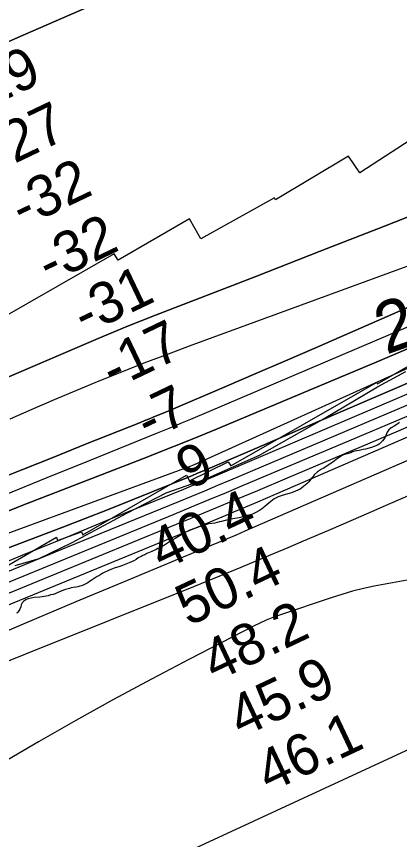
# Model space of a CAD drawing. Extents: x 3177385 to 3215275, y 903885 to 929304.
# Drawn here: x 3197368 to 3197989, y 912486 to 913822 of the extents above; entities that cross this region are included whole.
import ezdxf

# ---------------------------------------------------------------- set-up
doc = ezdxf.new("R2010")
doc.units = 0
for name, color, linetype in [('V-RIVR-EDGE', 7, 'Continuous'), ('V-RIVR-IDEN', 7, 'Continuous'), ('V-RIVR-RANG', 7, 'Continuous'), ('V-RRAP-RVMT', 7, 'Continuous'), ('V-SITE-VEGE', 7, 'Continuous'), ('V-TOPO-BNDY', 7, 'Continuous'), ('V-TOPO-DPTH', 7, 'Continuous'), ('V-TOPO-MAJR', 7, 'Continuous'), ('V-TOPO-MINR', 7, 'Continuous'), ('V-TOPO-WATR', 7, 'Continuous')]:
    doc.layers.add(name, color=color, linetype=linetype)

msp = doc.modelspace()

# ---------------------------------------------------------------- linework, layer by layer
at = {"layer": 'V-RIVR-EDGE'}
msp.add_lwpolyline([(3197365.4, 912930.6), (3197404.5, 912941.8), (3197458, 912967.8), (3197546.8, 913015.4), (3197610.4, 913048.7), (3197673.9, 913070.7), (3197762.2, 913109.6), (3197867.1, 913168.9), (3197953.3, 913220.4), (3197999.5, 913245.5)], dxfattribs=at)
at = {"layer": 'V-RRAP-RVMT'}
for points in [[(3198676.7, 913864.1), (3198655.3, 913896.8), (3198542.3, 913824.7), (3198538.1, 913830.1), (3198431.4, 913761.2), (3198410.7, 913790.5), (3198293, 913713.7), (3198279.5, 913731.9), (3198168.4, 913660.4), (3198123.3, 913659.6), (3198109.2, 913680.1), (3198031.3, 913630.7), (3198028.1, 913634.7), (3197925, 913567.7), (3197906.3, 913594.7), (3197788, 913524), (3197786.3, 913527.5), (3197666.9, 913460.6), (3197648.1, 913493.3), (3197532.6, 913426.2), (3197526.1, 913436.6), (3197292.5, 913302.6)], [(3197337.8, 912921.7), (3197432.4, 912976.4), (3197434.2, 912970.9), (3197473, 912985.2), (3197475.3, 912980.1), (3197643.3, 913077), (3197648.2, 913068.1), (3197711.1, 913098.9), (3197715.3, 913092.4), (3197951.6, 913227.8), (3197953.3, 913225.1), (3198007.2, 913256.1)]]:
    msp.add_lwpolyline(points, dxfattribs=at)
at = {"layer": 'V-SITE-VEGE'}
for p, q in [((3197980.4, 913156.6), (3197975.7, 913153.7)), ((3197986.7, 913160.2), (3197980.4, 913156.6)), ((3197989.2, 913162.4), (3197986.7, 913160.2)), ((3197969.1, 913147.1), (3197965.9, 913138.6)), ((3197972.1, 913150.5), (3197969.1, 913147.1)), ((3197975.7, 913153.7), (3197972.1, 913150.5)), ((3197956.1, 913127.2), (3197953.4, 913125.8)), ((3197958.5, 913129.4), (3197956.1, 913127.2)), ((3197961.5, 913132.8), (3197958.5, 913129.4)), ((3197963.7, 913135.5), (3197961.5, 913132.8)), ((3197965.9, 913138.6), (3197963.7, 913135.5)), ((3197912.9, 913114.8), (3197909.9, 913113.6)), ((3197919.2, 913116.7), (3197912.9, 913114.8)), ((3197923.6, 913117.2), (3197919.2, 913116.7)), ((3197930.2, 913118.6), (3197923.6, 913117.2)), ((3197933.9, 913119.1), (3197930.2, 913118.6)), ((3197943.6, 913121.9), (3197933.9, 913119.1)), ((3197953.4, 913125.8), (3197943.6, 913121.9)), ((3197886.5, 913102.3), (3197881.1, 913098.2)), ((3197895, 913108.3), (3197886.5, 913102.3)), ((3197898.5, 913110), (3197895, 913108.3)), ((3197901.9, 913111), (3197898.5, 913110)), ((3197909.9, 913113.6), (3197901.9, 913111)), ((3197865.2, 913088), (3197862.3, 913086.8)), ((3197868.1, 913089.5), (3197865.2, 913088)), ((3197871.8, 913092.4), (3197868.1, 913089.5)), ((3197881.1, 913098.2), (3197871.8, 913092.4)), ((3197848.8, 913075.2), (3197846.6, 913072)), ((3197850.5, 913077.9), (3197848.8, 913075.2)), ((3197855.9, 913082.7), (3197850.5, 913077.9)), ((3197862.3, 913086.8), (3197855.9, 913082.7)), ((3197839, 913063.3), (3197833.6, 913058.7)), ((3197841.9, 913066.5), (3197839, 913063.3)), ((3197846.6, 913072), (3197841.9, 913066.5)), ((3197810.3, 913047.2), (3197800.6, 913044.8)), ((3197814, 913048.3), (3197810.3, 913047.2)), ((3197820.4, 913051), (3197814, 913048.3)), ((3197827.9, 913054.6), (3197820.4, 913051)), ((3197830.4, 913056.5), (3197827.9, 913054.6)), ((3197833.6, 913058.7), (3197830.4, 913056.5)), ((3197780.3, 913034.2), (3197777.1, 913031.7)), ((3197785.9, 913038.8), (3197780.3, 913034.2)), ((3197792.5, 913042.1), (3197785.9, 913038.8)), ((3197800.6, 913044.8), (3197792.5, 913042.1)), ((3197765.4, 913022.1), (3197761.9, 913019.6)), ((3197767.8, 913024.2), (3197765.4, 913022.1)), ((3197770.5, 913026.2), (3197767.8, 913024.2)), ((3197777.1, 913031.7), (3197770.5, 913026.2)), ((3197729.2, 913007.9), (3197718.5, 913006.5)), ((3197737.7, 913010.3), (3197729.2, 913007.9)), ((3197741.2, 913011.5), (3197737.7, 913010.3)), ((3197744.6, 913012.4), (3197741.2, 913011.5)), ((3197748.7, 913013.4), (3197744.6, 913012.4)), ((3197751.7, 913014.6), (3197748.7, 913013.4)), ((3197755.1, 913015.8), (3197751.7, 913014.6)), ((3197761.9, 913019.6), (3197755.1, 913015.8)), ((3197665.7, 912993.6), (3197662.6, 912992.7)), ((3197672.3, 912996), (3197665.7, 912993.6)), ((3197675.7, 912996.8), (3197672.3, 912996)), ((3197679.2, 912997.9), (3197675.7, 912996.8)), ((3197684.5, 912998.6), (3197679.2, 912997.9)), ((3197689.2, 912999.1), (3197684.5, 912998.6)), ((3197697, 913001.3), (3197689.2, 912999.1)), ((3197700.4, 913002), (3197697, 913001.3)), ((3197714.1, 913005.5), (3197700.4, 913002)), ((3197718.5, 913006.5), (3197714.1, 913005.5)), ((3197636.7, 912981.9), (3197633.2, 912979.4)), ((3197648.9, 912987.9), (3197636.7, 912981.9)), ((3197655, 912990.3), (3197648.9, 912987.9)), ((3197658.4, 912991.2), (3197655, 912990.3)), ((3197662.6, 912992.7), (3197658.4, 912991.2)), ((3197614.4, 912967.9), (3197607.8, 912963.3)), ((3197617.6, 912969.8), (3197614.4, 912967.9)), ((3197620, 912971.7), (3197617.6, 912969.8)), ((3197624.9, 912974.6), (3197620, 912971.7)), ((3197627.9, 912976.1), (3197624.9, 912974.6)), ((3197633.2, 912979.4), (3197627.9, 912976.1)), ((3197587, 912953.4), (3197579, 912949.8)), ((3197594.3, 912956.3), (3197587, 912953.4)), ((3197597, 912958), (3197594.3, 912956.3)), ((3197600.2, 912959.2), (3197597, 912958)), ((3197603.6, 912961.1), (3197600.2, 912959.2)), ((3197607.8, 912963.3), (3197603.6, 912961.1)), ((3197561.6, 912940.4), (3197557.9, 912938.2)), ((3197565.3, 912942.8), (3197561.6, 912940.4)), ((3197569.7, 912945), (3197565.3, 912942.8)), ((3197572.8, 912946.9), (3197569.7, 912945)), ((3197575.8, 912948.1), (3197572.8, 912946.9)), ((3197579, 912949.8), (3197575.8, 912948.1)), ((3197535.2, 912929.1), (3197525.9, 912926.2)), ((3197539.6, 912930.3), (3197535.2, 912929.1)), ((3197550.3, 912935.1), (3197539.6, 912930.3)), ((3197557.9, 912938.2), (3197550.3, 912935.1)), ((3197501.2, 912913.9), (3197498.3, 912912.5)), ((3197504.7, 912915.8), (3197501.2, 912913.9)), ((3197507.6, 912918), (3197504.7, 912915.8)), ((3197516.9, 912922.6), (3197507.6, 912918)), ((3197520.8, 912924), (3197516.9, 912922.6)), ((3197525.9, 912926.2), (3197520.8, 912924)), ((3197480.2, 912900.6), (3197477, 912899.4)), ((3197483.1, 912902.3), (3197480.2, 912900.6)), ((3197486.1, 912904.3), (3197483.1, 912902.3)), ((3197489, 912906.4), (3197486.1, 912904.3)), ((3197492.2, 912908.4), (3197489, 912906.4)), ((3197498.3, 912912.5), (3197492.2, 912908.4)), ((3197437.2, 912887.7), (3197433.6, 912886.3)), ((3197444.1, 912890.6), (3197437.2, 912887.7)), ((3197447.2, 912891.6), (3197444.1, 912890.6)), ((3197453.6, 912893.2), (3197447.2, 912891.6)), ((3197456.5, 912894.2), (3197453.6, 912893.2)), ((3197459.7, 912894.9), (3197456.5, 912894.2)), ((3197463.8, 912895.6), (3197459.7, 912894.9)), ((3197467, 912895.8), (3197463.8, 912895.6)), ((3197470.2, 912896.8), (3197467, 912895.8)), ((3197473.1, 912897.3), (3197470.2, 912896.8)), ((3197477, 912899.4), (3197473.1, 912897.3)), ((3197383.5, 912875.1), (3197379.6, 912872.9)), ((3197386.7, 912876.3), (3197383.5, 912875.1)), ((3197396.2, 912878.7), (3197386.7, 912876.3)), ((3197405.5, 912879.1), (3197396.2, 912878.7)), ((3197409.1, 912879.8), (3197405.5, 912879.1)), ((3197412.3, 912880.1), (3197409.1, 912879.8)), ((3197418.9, 912881.5), (3197412.3, 912880.1)), ((3197422.8, 912882.7), (3197418.9, 912881.5)), ((3197427.2, 912883.6), (3197422.8, 912882.7)), ((3197430.6, 912884.8), (3197427.2, 912883.6)), ((3197433.6, 912886.3), (3197430.6, 912884.8)), ((3197374.4, 912863.5), (3197372.9, 912859.8)), ((3197375.4, 912866.9), (3197374.4, 912863.5)), ((3197376.7, 912869.8), (3197375.4, 912866.9)), ((3197379.6, 912872.9), (3197376.7, 912869.8)), ((3197368.5, 912853.8), (3197367.5, 912853)), ((3197371.2, 912856.9), (3197368.5, 912853.8)), ((3197372.9, 912859.8), (3197371.2, 912856.9))]:
    msp.add_line(p, q, dxfattribs=at)
at = {"layer": 'V-TOPO-BNDY'}
msp.add_lwpolyline([(3212104.8, 927455), (3211654.7, 925302.3), (3210557.1, 922651.3), (3209209.3, 920082.8), (3207894, 918536.9), (3206269, 917198.2), (3204190, 915875.2), (3202489, 914709.7), (3200914, 913922.2), (3198614.5, 912914.1), (3196094.5, 911748.6), (3194267.5, 911118.6), (3192913, 910488.6), (3191155.6, 909558.2), (3212939.7, 909531.5)], dxfattribs=at)
at = {"layer": 'V-TOPO-DPTH'}
for points in [[(3199243.5, 914059.7), (3199154.5, 914014.8), (3199065.5, 913970.1), (3198976.3, 913925.6), (3198887.1, 913881.3), (3198607.4, 913742.9), (3198578.8, 913729.2), (3198549.9, 913715.9), (3198520.8, 913703.3), (3198491.5, 913691.2), (3198173.5, 913564), (3198069.2, 913522.6), (3197964.9, 913481.3), (3197860.4, 913440.5), (3197755.9, 913399.8), (3197593.4, 913337), (3197570.1, 913327.8), (3197546.7, 913318.5), (3197523.5, 913308.9), (3197500.4, 913299.1), (3197177.6, 913160.9)], [(3197177.6, 913160.9), (3197500.4, 913299.1), (3197523.5, 913308.9), (3197546.7, 913318.5), (3197570.1, 913327.8), (3197593.4, 913337), (3197755.9, 913399.8), (3197860.4, 913440.5), (3197964.9, 913481.3), (3198069.2, 913522.6), (3198173.5, 913564), (3198491.5, 913691.2), (3198520.8, 913703.3), (3198549.9, 913715.9), (3198578.8, 913729.2), (3198607.4, 913742.9), (3198887.1, 913881.3), (3198976.3, 913925.6), (3199065.5, 913970.1), (3199154.5, 914014.8), (3199243.5, 914059.7)], [(3199473, 914010.7), (3198670.3, 913642.9), (3198634.5, 913626.6), (3198598.6, 913610.4), (3198562.7, 913594.4), (3198526.6, 913578.5), (3197899.9, 913304.1), (3197852, 913283.2), (3197804.2, 913262.5), (3197756.2, 913241.9), (3197708.3, 913221.4), (3197614.9, 913181.7), (3197613.6, 913181.1), (3197609.5, 913179.4), (3197597.7, 913174.6), (3197590.5, 913171.6), (3197583.2, 913168.7), (3197576, 913165.7), (3197568.7, 913162.8), (3197479.8, 913127.2), (3197428, 913106.5), (3197376.3, 913085.8), (3197324.6, 913065.1)], [(3199473, 914010.7), (3198670.3, 913642.9), (3198634.5, 913626.6), (3198598.6, 913610.4), (3198562.7, 913594.4), (3198526.6, 913578.5), (3197899.9, 913304.1), (3197852, 913283.2), (3197804.2, 913262.5), (3197756.2, 913241.9), (3197708.3, 913221.4), (3197614.9, 913181.7), (3197613.6, 913181.1), (3197609.5, 913179.4), (3197597.7, 913174.6), (3197590.5, 913171.6), (3197583.2, 913168.7), (3197576, 913165.7), (3197568.7, 913162.8), (3197479.8, 913127.2), (3197428, 913106.5), (3197376.3, 913085.8), (3197324.6, 913065.1)], [(3197355.4, 913781), (3197378.6, 913791.5), (3197836.6, 913991.1)], [(3197836.6, 913991.1), (3197378.6, 913791.5), (3197355.4, 913781)], [(3197264.2, 912925.1), (3197442.6, 912992.8), (3197479, 913006.7), (3197515.4, 913020.9), (3197551.7, 913035.4), (3197587.9, 913050), (3197646.6, 913074), (3197653.4, 913076.8), (3197660.1, 913079.6), (3197666.9, 913082.5), (3197673.7, 913085.3), (3198317.9, 913362.1), (3198372.8, 913385.9), (3198427.7, 913409.8), (3198482.4, 913434), (3198537, 913458.5), (3198562.5, 913469.9), (3198604.2, 913488.9), (3198645.9, 913508.1), (3198687.4, 913527.6), (3198728.8, 913547.2), (3199472.8, 913904.2)], [(3199472.8, 913904.2), (3198728.8, 913547.2), (3198687.4, 913527.6), (3198645.9, 913508.1), (3198604.2, 913488.9), (3198562.5, 913469.9), (3198537, 913458.5), (3198482.4, 913434), (3198427.7, 913409.8), (3198372.8, 913385.9), (3198317.9, 913362.1), (3197673.7, 913085.3), (3197666.9, 913082.5), (3197660.1, 913079.6), (3197653.4, 913076.8), (3197646.6, 913074), (3197587.9, 913050), (3197551.7, 913035.4), (3197515.4, 913020.9), (3197479, 913006.7), (3197442.6, 912992.8), (3197264.2, 912925.1)], [(3197337.3, 912914.1), (3197449.3, 912960.1), (3197631.3, 913034.5), (3197652.3, 913043.2), (3197673.3, 913051.9), (3197694.3, 913060.7), (3197715.2, 913069.5), (3198120.9, 913241.7), (3198211.2, 913280.1), (3198301.3, 913318.7), (3198391.4, 913357.6), (3198481.3, 913396.7), (3198636, 913464.1), (3198648.5, 913469.7), (3198661.1, 913475.3), (3198673.6, 913480.9), (3198686, 913486.7), (3198808.6, 913543.5), (3198882.4, 913577.8), (3198956.1, 913612.1), (3199029.8, 913646.5), (3199103.4, 913681), (3199497.9, 913865.8)], [(3197357.4, 913168.6), (3197393.3, 913184.5), (3197429.3, 913200.1), (3197465.5, 913215.3), (3197501.8, 913230.3), (3197538.3, 913244.9), (3197574.9, 913259.2), (3197611.6, 913273.2), (3197648.4, 913286.9), (3197995.5, 913414.4), (3198093.9, 913451.3), (3198192, 913489.1), (3198289.5, 913528.2), (3198386.7, 913568.2), (3198548, 913635.8), (3198564.2, 913642.8), (3198580.4, 913649.9), (3198596.5, 913657.2), (3198612.5, 913664.7), (3198747.1, 913729), (3198830.3, 913768.9), (3198913.3, 913809.1), (3198996.1, 913849.8)], [(3197357.4, 913168.6), (3197393.3, 913184.5), (3197429.3, 913200.1), (3197465.5, 913215.3), (3197501.8, 913230.3), (3197538.3, 913244.9), (3197574.9, 913259.2), (3197611.6, 913273.2), (3197648.4, 913286.9), (3197995.5, 913414.4), (3198093.9, 913451.3), (3198192, 913489.1), (3198289.5, 913528.2), (3198386.7, 913568.2), (3198548, 913635.8), (3198564.2, 913642.8), (3198580.4, 913649.9), (3198596.5, 913657.2), (3198612.5, 913664.7), (3198747.1, 913729), (3198830.3, 913768.9), (3198913.3, 913809.1), (3198996.1, 913849.8)], [(3197259.4, 912981.5), (3197385.1, 913031), (3197580.7, 913107), (3197608.7, 913118), (3197636.7, 913129.1), (3197664.5, 913140.5), (3197692.4, 913152), (3197850.9, 913218.1), (3197957.7, 913263.2), (3198064.3, 913308.9), (3198170.5, 913355.5), (3198276.4, 913402.6), (3198590.1, 913543.8), (3198606.4, 913551.1), (3198622.6, 913558.5), (3198638.8, 913566), (3198655, 913573.5), (3198807.5, 913644.8), (3198900, 913688), (3198992.4, 913731.2), (3199084.8, 913774.5), (3199177.2, 913817.7)], [(3199177.2, 913817.7), (3199084.8, 913774.5), (3198992.4, 913731.2), (3198900, 913688), (3198807.5, 913644.8), (3198655, 913573.5), (3198638.8, 913566), (3198622.6, 913558.5), (3198606.4, 913551.1), (3198590.1, 913543.8), (3198276.4, 913402.6), (3198170.5, 913355.5), (3198064.3, 913308.9), (3197957.7, 913263.2), (3197850.9, 913218.1), (3197692.4, 913152), (3197664.5, 913140.5), (3197636.7, 913129.1), (3197608.7, 913118), (3197580.7, 913107), (3197385.1, 913031), (3197259.4, 912981.5)]]:
    msp.add_lwpolyline(points, dxfattribs=at)
at = {"layer": 'V-TOPO-MAJR'}
msp.add_lwpolyline([(3196774.2, 912628), (3197668.9, 912996.2), (3197681.8, 913001.5), (3197694.7, 913006.9), (3197707.6, 913012.2), (3197720.4, 913017.6), (3197733.3, 913023), (3197746.2, 913028.4), (3197759, 913033.9), (3197771.8, 913039.4), (3198613, 913404), (3198646.7, 913418.8), (3198680.3, 913433.7), (3198713.8, 913448.8), (3198747.2, 913464.1), (3199437, 913783.1)], dxfattribs=at)
at = {"layer": 'V-TOPO-MINR'}
for points in [[(3197177.6, 913160.9), (3197500.4, 913299.1), (3197523.5, 913308.9), (3197546.7, 913318.5), (3197570.1, 913327.8), (3197593.4, 913337), (3197755.9, 913399.8), (3197860.4, 913440.5), (3197964.9, 913481.3), (3198069.2, 913522.6), (3198173.5, 913564), (3198491.5, 913691.2), (3198520.8, 913703.3), (3198549.9, 913715.9), (3198578.8, 913729.2), (3198607.4, 913742.9), (3198887.1, 913881.3), (3198976.3, 913925.6), (3199065.5, 913970.1), (3199154.5, 914014.8), (3199243.5, 914059.7)], [(3197324.6, 913065.1), (3197376.3, 913085.8), (3197428, 913106.5), (3197479.8, 913127.2), (3197568.7, 913162.8), (3197576, 913165.7), (3197583.2, 913168.7), (3197590.5, 913171.6), (3197597.7, 913174.6), (3197609.5, 913179.4), (3197613.6, 913181.1), (3197614.9, 913181.7), (3197708.3, 913221.4), (3197756.2, 913241.9), (3197804.2, 913262.5), (3197852, 913283.2), (3197899.9, 913304.1), (3198526.6, 913578.5), (3198562.7, 913594.4), (3198598.6, 913610.4), (3198634.5, 913626.6), (3198670.3, 913642.9), (3199473, 914010.7)], [(3197836.6, 913991.1), (3197378.6, 913791.5), (3197355.4, 913781)], [(3197348.7, 913045.1), (3197417.3, 913073.3), (3197486, 913101.2), (3197596.4, 913145.8), (3197610, 913151.3), (3197623.5, 913156.9), (3197637, 913162.5), (3197650.5, 913168.2), (3198360.9, 913470.2), (3198403, 913488.2), (3198445, 913506.4), (3198486.9, 913524.8), (3198528.7, 913543.4), (3198602.2, 913576.3), (3198607.3, 913578.6), (3198612.3, 913580.9), (3198617.3, 913583.2), (3198622.3, 913585.5), (3198670.5, 913607.9), (3198699.6, 913621.4), (3198728.7, 913635), (3198757.8, 913648.5), (3198786.9, 913662.1), (3199431.6, 913962.9)], [(3197337.3, 912914.1), (3197449.3, 912960.1), (3197631.3, 913034.5), (3197652.3, 913043.2), (3197673.3, 913051.9), (3197694.3, 913060.7), (3197715.2, 913069.5), (3198120.9, 913241.7), (3198211.2, 913280.1), (3198301.3, 913318.7), (3198391.4, 913357.6), (3198481.3, 913396.7), (3198636, 913464.1), (3198648.5, 913469.7), (3198661.1, 913475.3), (3198673.6, 913480.9), (3198686, 913486.7), (3198808.6, 913543.5), (3198882.4, 913577.8), (3198956.1, 913612.1), (3199029.8, 913646.5), (3199103.4, 913681), (3199497.9, 913865.8)], [(3197357.4, 913168.6), (3197393.3, 913184.5), (3197429.3, 913200.1), (3197465.5, 913215.3), (3197501.8, 913230.3), (3197538.3, 913244.9), (3197574.9, 913259.2), (3197611.6, 913273.2), (3197648.4, 913286.9), (3197995.5, 913414.4), (3198093.9, 913451.3), (3198192, 913489.1), (3198289.5, 913528.2), (3198386.7, 913568.2), (3198548, 913635.8), (3198564.2, 913642.8), (3198580.4, 913649.9), (3198596.5, 913657.2), (3198612.5, 913664.7), (3198747.1, 913729), (3198830.3, 913768.9), (3198913.3, 913809.1), (3198996.1, 913849.8)], [(3197259.4, 912981.5), (3197385.1, 913031), (3197580.7, 913107), (3197608.7, 913118), (3197636.7, 913129.1), (3197664.5, 913140.5), (3197692.4, 913152), (3197850.9, 913218.1), (3197957.7, 913263.2), (3198064.3, 913308.9), (3198170.5, 913355.5), (3198276.4, 913402.6), (3198590.1, 913543.8), (3198606.4, 913551.1), (3198622.6, 913558.5), (3198638.8, 913566), (3198655, 913573.5), (3198807.5, 913644.8), (3198900, 913688), (3198992.4, 913731.2), (3199084.8, 913774.5), (3199177.2, 913817.7)], [(3197101.8, 912890.4), (3197651, 913092.3), (3197653.6, 913093.3), (3197657.6, 913094.9), (3197661.5, 913096.6), (3198578, 913511.1), (3198605.5, 913523.6), (3198632.9, 913536.2), (3198660.3, 913548.9), (3198687.7, 913561.7), (3199109.8, 913759.7), (3199178.1, 913791.8)], [(3197284.3, 912875), (3197623.3, 913013.9), (3197651.8, 913025.6), (3197680.2, 913037.4), (3197708.6, 913049.2), (3197736.9, 913061.2), (3197896.4, 913128.4), (3198004.4, 913174.2), (3198112.4, 913220.2), (3198220.1, 913266.6), (3198327.8, 913313.3), (3198628.3, 913444.1), (3198647.9, 913452.7), (3198667.5, 913461.4), (3198687, 913470.2), (3198706.4, 913479.2), (3198915.5, 913576), (3199022.6, 913625.8), (3199129.8, 913675.6), (3199236.8, 913725.5)], [(3197035.8, 912754.8), (3197615.1, 912992.6), (3197651.2, 913007.5), (3197687.3, 913022.4), (3197723.3, 913037.4), (3197759.4, 913052.5), (3197807.5, 913072.7), (3197867.5, 913098), (3197927.4, 913123.4), (3197987.3, 913149.1), (3198047.1, 913174.9), (3198620.6, 913424), (3198647.3, 913435.7), (3198673.9, 913447.5), (3198700.4, 913459.5), (3198726.8, 913471.7), (3199175, 913679.1)], [(3197106.7, 912676.6), (3197655.3, 912896.6), (3197693.8, 912912.2), (3197732.2, 912927.9), (3197770.5, 912943.8), (3197808.7, 912959.9), (3197829.6, 912968.7), (3197878.2, 912989.5), (3197926.8, 913010.4), (3197975.2, 913031.6), (3198023.5, 913053), (3198665.1, 913338.9), (3198689.5, 913349.8), (3198713.9, 913360.7), (3198738.3, 913371.7), (3198762.7, 913382.7), (3199246.2, 913601.4)], [(3197301.4, 912915.8), (3197374.3, 912946.1), (3197447.4, 912976.2), (3197520.4, 913006.1), (3197639, 913054.6), (3197652.8, 913060.2), (3197666.6, 913066), (3197680.4, 913071.7), (3197694.1, 913077.6), (3198414.1, 913384.7)], [(3197301.5, 912803.1), (3197383, 912837.7), (3197464.7, 912872.1), (3197546.5, 912906.2), (3197681.3, 912962.2), (3197695.7, 912968.2), (3197710.1, 912974.3), (3197724.5, 912980.5), (3197738.9, 912986.7), (3198542.4, 913335.8)], [(3198192, 912936.1), (3198187, 912935.6), (3198019.8, 912909.7), (3198001.8, 912906.8), (3197983.9, 912903.7), (3197966.1, 912900.4), (3197948.2, 912896.9), (3197930.5, 912893), (3197912.9, 912888.7), (3197895.5, 912883.6), (3197878.2, 912878.2), (3197794.5, 912850.1), (3197783.6, 912846.2), (3197772.9, 912841.9), (3197762.4, 912837.2), (3197752, 912832.1), (3197648.3, 912778.7), (3197586.5, 912746.1), (3197525, 912713), (3197464, 912678.8), (3197403.4, 912644.1), (3197138.1, 912489), (3197101.9, 912467.6)]]:
    msp.add_lwpolyline(points, dxfattribs=at)
at = {"layer": 'V-TOPO-WATR'}
msp.add_lwpolyline([(3197264.2, 912925.1), (3197442.6, 912992.8), (3197479, 913006.7), (3197515.4, 913020.9), (3197551.7, 913035.4), (3197587.9, 913050), (3197646.6, 913074), (3197653.4, 913076.8), (3197660.1, 913079.6), (3197666.9, 913082.5), (3197673.7, 913085.3), (3198317.9, 913362.1), (3198372.8, 913385.9), (3198427.7, 913409.8), (3198482.4, 913434), (3198537, 913458.5), (3198562.5, 913469.9), (3198604.2, 913488.9), (3198645.9, 913508.1), (3198687.4, 913527.6), (3198728.8, 913547.2), (3199472.8, 913904.2)], dxfattribs=at)

# ---------------------------------------------------------------- texts
at = {"layer": 'V-RIVR-IDEN'}
msp.add_text('2012', height=83, rotation=19.6344, dxfattribs=at).set_placement((3197967.4, 913272.4))
at = {"layer": 'V-RIVR-RANG'}
for s, rotation, p in [('-29', 25.5422, (3197294.9, 913660)), ('-27', 25.5422, (3197337.5, 913569.5)), ('-32', 25.5422, (3197377.5, 913477.8)), ('-32', 25.5422, (3197420.4, 913387.5)), ('-31', 25.5422, (3197478.3, 913304.3)), ('-17', 25.5422, (3197524.3, 913215.4)), ('-7', 25.5422, (3197580.9, 913131.7)), ('9', 25.5422, (3197647.8, 913052.8)), ('40.4', 25.2483, (3197603.7, 912921.5)), ('50.4', 25.2483, (3197646.5, 912831.2)), ('48.2', 25.2483, (3197689.4, 912740.9)), ('45.9', 25.2483, (3197732.1, 912650.4)), ('46.1', 25.2483, (3197777.3, 912561.2))]:
    msp.add_text(s, height=67, rotation=rotation, dxfattribs=at).set_placement(p)

doc.saveas('drawing.dxf')
